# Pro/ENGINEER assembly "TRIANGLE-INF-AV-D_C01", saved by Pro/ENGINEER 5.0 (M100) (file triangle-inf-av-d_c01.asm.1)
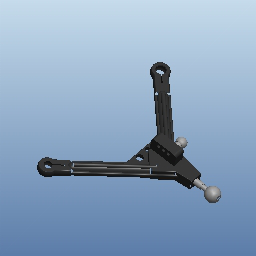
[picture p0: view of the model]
Units: millimeter Newton Second (mmNs); MM, TONNE, HOURS

Other components: 80657301-TRI_INF_AV_COMPL_C01, 80462600-ROTULE_D14_C01, 80657301-TRIANG_AV_INF_COMP_C01, E-ROTULE_VIS_C02

Other named items: A-DROITE, A-DESSUS, A-FACE, A-R0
